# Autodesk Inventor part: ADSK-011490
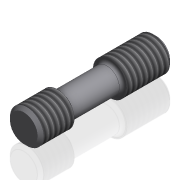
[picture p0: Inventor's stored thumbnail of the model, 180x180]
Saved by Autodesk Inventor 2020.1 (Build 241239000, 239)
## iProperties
Created: 2000-02
Part Number: ADSK-011490
Material: RA HRS
Vendor: A084664
Document SubType Name: Modeling
Designer: dmcquary
Density: 7.83 g/cm^3
Appearance: Métal - Acier
Mass: 10.1792 g
Surface Area: 8.22472 cm^2
Volume: 1.30002 cm^3
Control State: 0
Checked Out: False
Master: False
Shininess: 0.0
Length Units: 11269
Angle Units: 11279
Time Units: 11290
Mass Units: 11283
Length Display Precision: 3
Angle Display Precision: 2
Compacted: True
Dimensions: 8x8x31,5 mm
Mass: 0,01 kg
Density: 0.0
Volumn: 0.0
Area: 0.0
PropertySet Name: Model Information
Author: dmcquary
Revision Number: -
Title: ADSK-011490
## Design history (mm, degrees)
feature "Gewinde1" dims "d13" = 7.25, "d14" = 0
feature "Gewinde2" dims "d15" = 10.25, "d16" = 0
node "Solide1"
  node "Extrusion1" dims "d1" = 11, "d2" = 0
  node "Extrusion2" dims "d4" = 12.5, "d5" = 0
  node "Extrusion3" dims "d7" = 8, "d8" = 0
  node "Fillet1" dims "d9" = 0.75
  node "Chamfer1" dims "d10" = 0.75, "d11" = 0.75, "d12" = 45 deg
sketch "Sketch1"
  geometry: C1 r 4 at (0, 0); 1 further point
  constraints: 1 centre point, 1 coincident
  dimensions: "d0" = 8 diameter of C1
sketch "Sketch2"
  geometry: C1 r 4 at (0, 0) reference; C2 r 3 at (0, 0)
  constraints: 1 centre point, 1 coincident
  dimensions: "d3" = 6 diameter of C2
sketch "Sketch3"
  geometry: C1 r 3 at (0, 0) reference; C2 r 4 at (0, 0)
  constraints: 1 centre point, 1 coincident
  dimensions: "d6" = 8 diameter of C2
node "Corps solides"
node "Corps surfaciques"
